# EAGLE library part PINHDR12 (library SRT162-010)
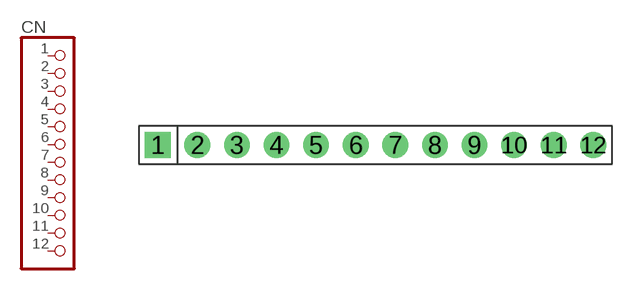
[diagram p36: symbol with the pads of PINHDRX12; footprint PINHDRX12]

Designator prefix CN

## PINHDR12  [PINHDRX12]
1  1  pas
2  2  pas
3  3  pas
4  4  pas
5  5  pas
6  6  pas
7  7  pas
8  8  pas
9  9  pas
10  10  pas
11  11  pas
12  12  pas

## Footprint PINHDRX12 (pad centres in mm)
drill 1.1 square: 1 -13.97,0
drill 1.1 round: 2 -11.43,0; 3 -8.89,0; 4 -6.35,0; 5 -3.81,0; 6 -1.27,0; 7 1.27,0; 8 3.81,0; 9 6.35,0; 10 8.89,0; 11 11.43,0; 12 13.97,0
